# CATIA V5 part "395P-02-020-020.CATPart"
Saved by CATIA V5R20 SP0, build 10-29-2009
Part number: 395P-02-020-020
Source: Unknown
Property "ARTICLENO": "395P-02-020-020"
Property "BOMINFO": "395P-02-020-020"
Property "CODE": "395P-02-020-020"
Property "D": "20.000"
Property "D1": "16.000"
Property "L": "68.000"
Property "L1": "34.000"
Property "L2": "6.000"
Property "L3": "22.000"
Property "L4": "3.000"
Property "LINA": "395P-02-020-020"
Property "M": "20.000"
Property "MAXLOAD": "500 Kg"
Property "MDW": "1000 Kg"
Property "NB": "395P-02-020-020"
Property "NBSYN": "$CODE."
Property "NN": "395P"
Property "NT": "VDI 3366 Lifting Pins"
Property "R": "5.000"
Property "R1": "8.000"
Property "SUPPLIER": "CF"
Property "SW": "30.000"
Bounding box of the stored display mesh (mm): x -15 to 15, y -34 to 34, z -17.321 to 17.321
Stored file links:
  C:\Users\Utente\Desktop\3D files 395P\395P-02-020-020.CATPart
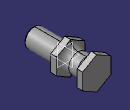
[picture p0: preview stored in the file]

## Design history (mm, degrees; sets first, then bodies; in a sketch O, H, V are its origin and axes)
Body1 "Geometry.1" (main body)
  Solid1 "395P-02-020-020.catpart": solid without history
